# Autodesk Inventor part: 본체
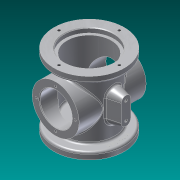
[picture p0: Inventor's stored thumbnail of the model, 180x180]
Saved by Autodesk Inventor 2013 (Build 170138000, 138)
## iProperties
Created: 2018-02
Part Number: 본체
Material: 알루미늄 6061
Document SubType Name: Modeling
Designer: Administrator
Density: 2.71 g/cm^3
Mass: 771.486 g
Surface Area: 822.531 cm^2
Volume: 284.681 cm^3
Author: Administrator
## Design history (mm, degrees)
sketch "스케치5"
  geometry: C1 r 38 at (0, 0); 1 further point
  constraints: 1 centre point, 1 coincident
  dimensions: "d5" = 76 diameter of C1
extrude "돌출2" new body sketch "스케치5" distance "d6" = 108; taper "d7" = 0 deg
sketch "스케치6"
  geometry: C1 r 52.5 at (0, 0); C2 r 38 at (0, 0); 1 further point
  constraints: 2 centre point, 2 coincident
  dimensions: "d9" = 105 diameter of C1; "d10" = 76 diameter of C2
extrude "돌출3" join sketch "스케치6" distance "d11" = 10; taper "d12" = 0 deg
node "작업 평면1"
sketch "스케치7"
  geometry: C1 r 52.5 at (0, 0) reference; C2 r 34 at (0, 0)
  constraints: 1 centre point, 1 coincident
  dimensions: "d14" = 68 diameter of C2
extrude "돌출4" cut sketch "스케치7" distance "d15" = 16; taper "d16" = 0 deg
sketch "스케치8"
  geometry: C1 r 52.5 at (0, 0) reference; C2 r 37 at (0, 0)
  constraints: 1 centre point, 1 coincident
  dimensions: "d17" = 74 diameter of C2
extrude "돌출5" cut sketch "스케치8" distance "d19" = 7; taper "d20" = 0 deg
sketch "스케치9"
  geometry: C1 r 37 at (0, 0) reference; C2 r 33 at (0, 0)
  constraints: 1 centre point, 1 coincident
  dimensions: "d22" = 66 diameter of C2
extrude "돌출6" cut sketch "스케치9" distance "d23" = 79; taper "d24" = 0 deg
node "작업 평면2"
sketch "스케치10"
  geometry: L1 (34, 0)-(-34, 0) reference; L2 (0, 0)-(0, 54); C1 r 35 at (0, 54)
  constraints: 2 end point, 1 centre point, 1 coincident, 1 perpendicular
  dimensions: "d26" = 54 distance of L2.start L2.end; "d27" = 70 diameter of C1
extrude "돌출7" join sketch "스케치10" stored distance "d28" = 79; taper "d29" = 0 deg
sketch "스케치11"
  geometry: C1 r 35 at (0, 0) reference; 2 further points
  constraints: 1 vertical alignment
  dimensions: "d30" = 29 distance of C1.centre point (0, 29)
hole "구멍1" sketch "스케치11" at (0, 29) diameter "d31" = 3.242; stored, may be unused: countersink angle "d35" = 90 deg, drill point angle "d37" = 118 deg; dims "d32" = 4, "d33" = 4, "d34" = 2, "d36" = 6
sketch "스케치12"
  geometry: C1 r 35 at (0, 0) reference; C2 r 24 at (0, 0); 1 further point
  constraints: 1 centre point, 1 coincident
  dimensions: "d41" = 48 diameter of C2
extrude "돌출9" cut sketch "스케치12" stored distance "d44" = 79; taper "d45" = 0 deg
sketch "스케치13"
  geometry: L1 (35, 50)-(-35, 50) reference; L2 (35, -50)-(-35, -50) reference; C1 r 33 at (0, 0) reference; C2 r 5 at (0, 0)
  constraints: 1 centre point, 1 coincident
  dimensions: "d46" = 10 diameter of C2
extrude "돌출10" cut sketch "스케치13" stored distance "d47" = 79; taper "d48" = 0 deg
node "작업 평면3"
sketch "스케치18"
  geometry: L1 (0, 0)-(54, 0); L2 (54, 0)-(54, -7); L3 (54, -7)-(41, -7); L4 (41, 0)-(41, 7); L5 (41, 7)-(67, 7); L6 (67, 7)-(67, 0); L7 (67, -7)-(41, -7); A1 r 7 centre (41, 0) between (41, 7) and (41, -7); A2 r 7 centre (67, 0) between (67, -7) and (67, 7)
  constraints: 14 end point, 4 perpendicular, 4 point on circle, 2 centre point, 2 point on line, 1 horizontal, 1 parallel, 1 tangent
  dimensions: "d77" = 54 distance of L1.start L1.end; "d78" = 7 distance of L1.end L2.end; "d79" = 13 distance of L2.end L3.end; "d80" = 14 distance of L4.end L3.end; "d81" = 26 distance of L4.end L5.end; "d82" = 14 distance of L5.end L7.start
extrude "돌출14" join sketch "스케치18" stored distance "d83" = 79; taper "d84" = 15 deg
sketch "스케치20"
  geometry: A1 r 7 centre (0, 41) between (-7, 41) and (7, 41) reference; A2 r 7 centre (0, 67) between (7, 67) and (-7, 67) reference; 3 further points
  constraints: 2 coincident
hole "구멍2" sketch "스케치20" at (0, 67), (0, 41) diameter "d85" = 4.134; stored, may be unused: countersink angle "d89" = 90 deg, drill point angle "d91" = 118 deg; dims "d86" = 6, "d87" = 4, "d88" = 2, "d90" = 8
sketch "스케치21"
  geometry: C1 r 37 at (0, 0) reference; 1 further point
  constraints: 1 vertical alignment
  dimensions: "d92" = 45 distance of C1.centre point (0, 45)
hole "구멍3" sketch "스케치21" at (0, 45) diameter "d93" = 4.134; stored, may be unused: countersink angle "d97" = 90 deg, drill point angle "d99" = 118 deg; dims "d94" = 4, "d95" = 4, "d96" = 2, "d98" = 6
sketch "스케치22"
  geometry: C1 r 52.5 at (0, 0) reference; C2 r 43 at (0, 0)
  constraints: 1 centre point, 1 coincident, 1 other
  dimensions: "d103" = 86 diameter of C2
feature "엠보싱1" sketch "스케치22" dims "d6" = 108, "d17" = 74, "d104" = 0.5, "d105" = 0
chamfer "모따기1" distance "d106" = 1; stored, may be unused: second distance "d107" = 2, angle "d108" = 45 deg
fillet "모깎기1" dims "d109" = 3
fillet "모깎기2" dims "d110" = 3
fillet "모깎기3" dims "d111" = 3
fillet "모깎기4" dims "d112" = 3
fillet "모깎기5" dims "d113" = 3
fillet "모깎기6" dims "d114" = 3
node "솔리드2"
mirror "대칭1"
pattern_circular "원형 패턴1" dims angle "d39" = 360 deg
mirror "대칭3"
pattern_circular "원형 패턴2" dims angle "d101" = 360 deg
other parameters: "d13" = 54, "d49" = 55
